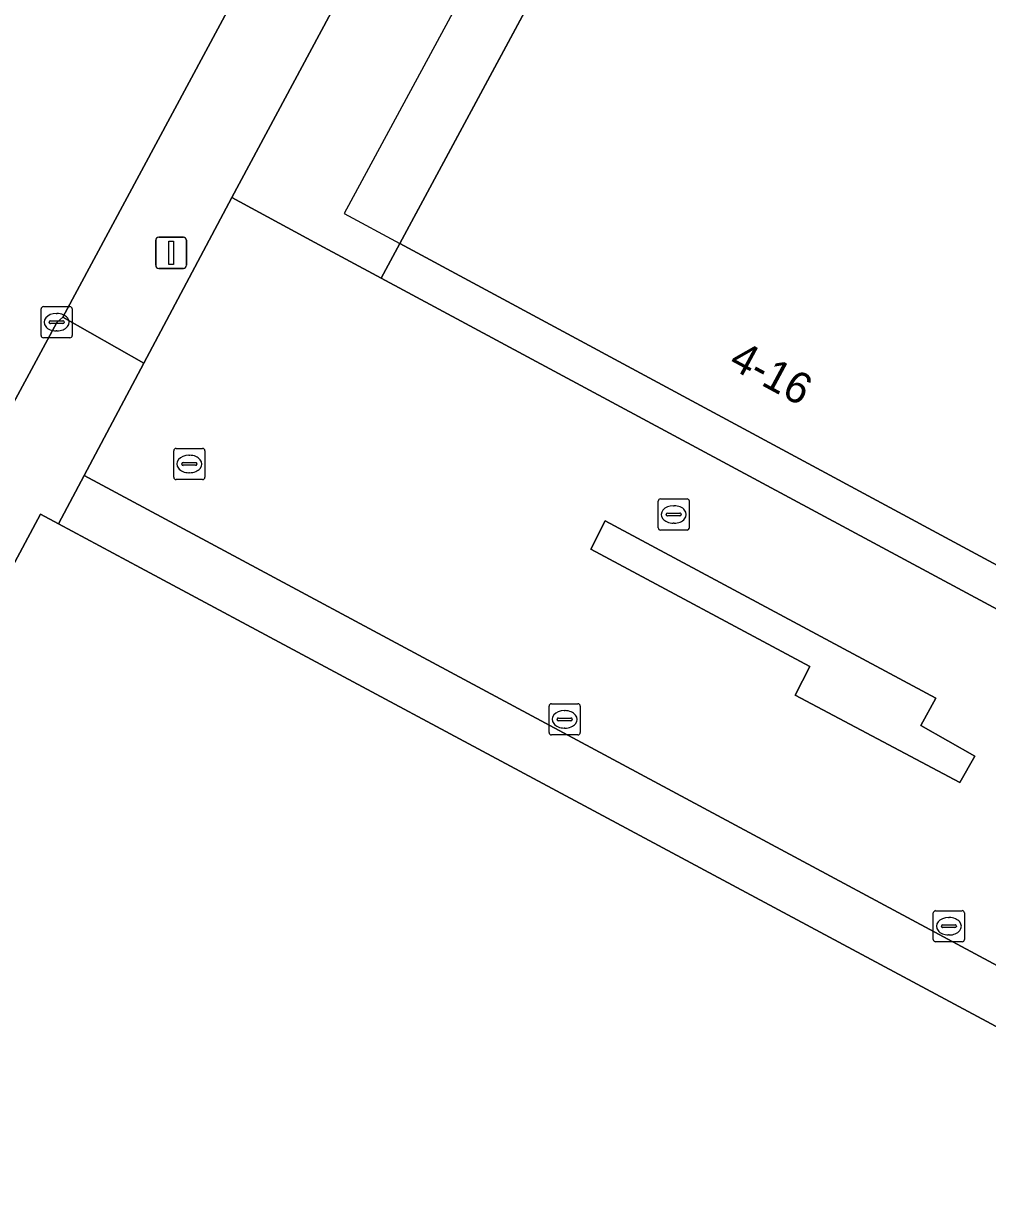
# Model space of a CAD drawing. Extents: x 159489 to 160304, y 383825 to 384531.
# Drawn here: x 159916.31 to 159947.25, y 384180.66 to 384218.65 of the extents above; entities that cross this region are included whole.
import ezdxf

# ---------------------------------------------------------------- set-up
doc = ezdxf.new("R2010")
doc.units = 0
for name, color, linetype in [('IMGEO_Groenvoorziening', 7, 'Continuous'), ('IMGEO_Kolk', 7, 'Continuous'), ('IMGEO_Lichtmast', 7, 'Continuous'), ('IMGEO_OVBaan_gesloten', 7, 'Continuous'), ('IMGEO_Pand', 7, 'Continuous'), ('IMGEO_Pand_nummerreeks', 7, 'Continuous'), ('IMGEO_Pand_overbouw', 7, 'Continuous'), ('IMGEO_Rioolput', 7, 'Continuous'), ('IMGEO_Voetpad_open', 7, 'Continuous')]:
    doc.layers.add(name, color=color, linetype=linetype)

msp = doc.modelspace()

# ---------------------------------------------------------------- linework, layer by layer
at = {"layer": 'IMGEO_Groenvoorziening'}
for points in [[(159982.197, 384221.174), (159967.686, 384229.02), (159951.577, 384199.109), (159928.39, 384211.596), (159927.794, 384210.489), (159967.949, 384188.903), (159982.328, 384181.173), (159984.895, 384182.371), (159986.818, 384178.787), (159991.4, 384176.315), (159993.92, 384177.521), (159995.948, 384173.906), (160023.092, 384159.367), (160025.82, 384157.906), (160029.234, 384164.348)], [(159946.374, 384194.291), (159946.851, 384195.146), (159945.113, 384196.129), (159945.604, 384197.003), (159934.981, 384202.69), (159934.517, 384201.79), (159941.552, 384198.022), (159941.079, 384197.098)]]:
    msp.add_lwpolyline(points, close=True, dxfattribs=at)
at = {"layer": 'IMGEO_Kolk'}
for p, q in [((159916.867, 384208.644), (159916.867, 384209.496)), ((159916.942, 384209.57), (159917.794, 384209.57)), ((159917.868, 384209.496), (159917.868, 384208.644)), ((159917.126, 384209.064), (159917.126, 384209.076)), ((159917.169, 384209.113), (159917.567, 384209.113)), ((159917.355, 384209.35), (159917.38, 384209.35)), ((159917.61, 384209.076), (159917.61, 384209.064)), ((159917.564, 384209.027), (159917.166, 384209.027)), ((159917.378, 384208.79), (159917.353, 384208.79)), ((159917.794, 384208.57), (159916.942, 384208.57)), ((159936.758, 384203.4), (159937.61, 384203.4)), ((159936.683, 384202.474), (159936.683, 384203.326)), ((159937.171, 384203.18), (159937.196, 384203.18)), ((159937.684, 384203.326), (159937.684, 384202.474)), ((159936.942, 384202.894), (159936.942, 384202.906)), ((159937.38, 384202.857), (159936.982, 384202.857)), ((159936.985, 384202.943), (159937.383, 384202.943)), ((159937.194, 384202.62), (159937.169, 384202.62)), ((159937.426, 384202.906), (159937.426, 384202.894)), ((159937.61, 384202.4), (159936.758, 384202.4)), ((159933.18, 384195.897), (159933.18, 384196.749)), ((159933.255, 384196.823), (159934.107, 384196.823)), ((159933.668, 384196.603), (159933.693, 384196.603)), ((159934.181, 384196.749), (159934.181, 384195.897)), ((159933.439, 384196.317), (159933.439, 384196.329)), ((159933.877, 384196.28), (159933.479, 384196.28)), ((159933.482, 384196.366), (159933.88, 384196.366)), ((159933.923, 384196.329), (159933.923, 384196.317)), ((159934.107, 384195.823), (159933.255, 384195.823)), ((159933.691, 384196.043), (159933.666, 384196.043)), ((159945.518, 384189.256), (159945.518, 384190.108)), ((159945.593, 384190.182), (159946.445, 384190.182)), ((159946.519, 384190.108), (159946.519, 384189.256)), ((159945.777, 384189.676), (159945.777, 384189.688)), ((159945.82, 384189.725), (159946.218, 384189.725)), ((159946.006, 384189.962), (159946.031, 384189.962)), ((159946.261, 384189.688), (159946.261, 384189.676)), ((159946.215, 384189.639), (159945.817, 384189.639)), ((159946.029, 384189.402), (159946.004, 384189.402)), ((159946.445, 384189.182), (159945.593, 384189.182))]:
    msp.add_line(p, q, dxfattribs=at)
for points in [[(159916.867, 384208.644), (159916.867, 384209.496)], [(159916.942, 384209.57), (159917.794, 384209.57)], [(159917.868, 384209.496), (159917.868, 384208.644)], [(159917.794, 384208.57), (159916.942, 384208.57)], [(159936.758, 384203.4), (159937.61, 384203.4)], [(159936.683, 384202.474), (159936.683, 384203.326)], [(159937.684, 384203.326), (159937.684, 384202.474)], [(159937.61, 384202.4), (159936.758, 384202.4)], [(159933.18, 384195.897), (159933.18, 384196.749)], [(159933.255, 384196.823), (159934.107, 384196.823)], [(159934.181, 384196.749), (159934.181, 384195.897)], [(159934.107, 384195.823), (159933.255, 384195.823)], [(159945.518, 384189.256), (159945.518, 384190.108)], [(159945.593, 384190.182), (159946.445, 384190.182)], [(159946.519, 384190.108), (159946.519, 384189.256)], [(159946.445, 384189.182), (159945.593, 384189.182)]]:
    msp.add_lwpolyline(points, dxfattribs=at)
for centre, radius, start, end in [((159916.944, 384209.494), 0.0765, 91.552, 178.448), ((159916.944, 384209.494), 0.0765, 91.552, 178.448), ((159917.792, 384209.494), 0.0765, 1.552, 88.448), ((159917.792, 384209.494), 0.0765, 1.552, 88.448), ((159917.166, 384209.073), 0.0403, 85.8775, 175.7526), ((159917.571, 384209.075), 0.0386, 1.7309, 96.639), ((159917.163, 384209.063), 0.0366, 178.938, 274.7102), ((159917.567, 384209.07), 0.043, 264.8664, 352.4533), ((159916.944, 384208.646), 0.0765, 181.552, 268.448), ((159916.944, 384208.646), 0.0765, 181.552, 268.448), ((159917.792, 384208.646), 0.0765, 271.552, 358.448), ((159917.792, 384208.646), 0.0765, 271.552, 358.448), ((159936.76, 384203.324), 0.0765, 91.552, 178.448), ((159936.76, 384203.324), 0.0765, 91.552, 178.448), ((159937.608, 384203.324), 0.0765, 1.552, 88.448), ((159937.608, 384203.324), 0.0765, 1.552, 88.448), ((159936.982, 384202.903), 0.0403, 85.8775, 175.7526), ((159936.979, 384202.893), 0.0366, 178.938, 274.7102), ((159937.383, 384202.9), 0.043, 264.8664, 352.4533), ((159937.387, 384202.905), 0.0386, 1.7309, 96.639), ((159936.76, 384202.476), 0.0765, 181.552, 268.448), ((159936.76, 384202.476), 0.0765, 181.552, 268.448), ((159937.608, 384202.476), 0.0765, 271.552, 358.448), ((159937.608, 384202.476), 0.0765, 271.552, 358.448), ((159933.257, 384196.747), 0.0765, 91.552, 178.448), ((159933.257, 384196.747), 0.0765, 91.552, 178.448), ((159934.105, 384196.747), 0.0765, 1.552, 88.448), ((159934.105, 384196.747), 0.0765, 1.552, 88.448), ((159933.479, 384196.326), 0.0403, 85.8775, 175.7526), ((159933.476, 384196.316), 0.0366, 178.938, 274.7102), ((159933.88, 384196.323), 0.043, 264.8664, 352.4533), ((159933.884, 384196.328), 0.0386, 1.7309, 96.639), ((159933.257, 384195.899), 0.0765, 181.552, 268.448), ((159933.257, 384195.899), 0.0765, 181.552, 268.448), ((159934.105, 384195.899), 0.0765, 271.552, 358.448), ((159934.105, 384195.899), 0.0765, 271.552, 358.448), ((159945.595, 384190.106), 0.0765, 91.552, 178.448), ((159945.595, 384190.106), 0.0765, 91.552, 178.448), ((159946.443, 384190.106), 0.0765, 1.552, 88.448), ((159946.443, 384190.106), 0.0765, 1.552, 88.448), ((159945.817, 384189.685), 0.0403, 85.8775, 175.7526), ((159946.222, 384189.687), 0.0386, 1.7309, 96.639), ((159945.814, 384189.675), 0.0366, 178.938, 274.7102), ((159946.218, 384189.682), 0.043, 264.8664, 352.4533), ((159945.595, 384189.258), 0.0765, 181.552, 268.448), ((159945.595, 384189.258), 0.0765, 181.552, 268.448), ((159946.443, 384189.258), 0.0765, 271.552, 358.448), ((159946.443, 384189.258), 0.0765, 271.552, 358.448)]:
    msp.add_arc(centre, radius, start, end, dxfattribs=at)
for centre, major_axis, ratio, start_param, end_param in [((159917.354, 384209.07), (-0.387, 0.002), 0.722429, 4.712389, 7.853982), ((159917.379, 384209.07), (-0.39, 0.002), 0.717154, 1.570796, 4.712389), ((159937.17, 384202.9), (-0.387, 0.002), 0.722429, 4.712389, 7.853982), ((159937.195, 384202.9), (-0.39, 0.002), 0.717154, 1.570796, 4.712389), ((159933.667, 384196.323), (-0.387, 0.002), 0.722429, 4.712389, 7.853982), ((159933.692, 384196.323), (-0.39, 0.002), 0.717154, 1.570796, 4.712389), ((159946.005, 384189.682), (-0.387, 0.002), 0.722429, 4.712389, 7.853982), ((159946.03, 384189.682), (-0.39, 0.002), 0.717154, 1.570796, 4.712389)]:
    msp.add_ellipse(centre, major_axis=major_axis, ratio=ratio, start_param=start_param, end_param=end_param, dxfattribs=at)
at = {"layer": 'IMGEO_Lichtmast'}
for p, q in [((159920.649, 384211.799), (159921.439, 384211.799)), ((159921.439, 384211.799), (159920.649, 384211.799)), ((159920.549, 384210.899), (159920.549, 384211.699)), ((159920.549, 384211.699), (159920.549, 384210.899)), ((159921.539, 384211.699), (159921.539, 384210.899)), ((159921.539, 384210.899), (159921.539, 384211.699)), ((159921.439, 384210.799), (159920.649, 384210.799)), ((159920.649, 384210.799), (159921.439, 384210.799))]:
    msp.add_line(p, q, dxfattribs=at)
msp.add_lwpolyline([(159920.969, 384211.674), (159921.119, 384211.674), (159921.119, 384210.924), (159920.969, 384210.924), (159920.969, 384211.674)], dxfattribs=at)
for centre, start, end in [((159920.649, 384211.699), 90, 180), ((159920.649, 384211.699), 90, 180), ((159921.439, 384211.699), 0, 90), ((159921.439, 384211.699), 360, 90), ((159920.649, 384210.899), 180, 270), ((159920.649, 384210.899), 180, 270), ((159921.439, 384210.899), 270, 0), ((159921.439, 384210.899), 270, 0)]:
    msp.add_arc(centre, 0.1, start, end, dxfattribs=at)
at = {"layer": 'IMGEO_OVBaan_gesloten'}
msp.add_lwpolyline([(159889.629, 384157.595), (159891.699, 384161.454), (159894.341, 384166.312), (159894.932, 384167.392), (159899.663, 384176.232), (159917.37, 384209.066), (159917.564, 384209.236), (159933.717, 384239.272), (159933.611, 384239.33), (159934.188, 384240.289), (159934.691, 384241.032), (159927.855, 384244.699), (159927.163, 384242.784), (159925.839, 384239.117), (159925.093, 384237.495), (159923.939, 384235.4), (159923.428, 384234.441), (159911.615, 384212.316), (159911.69, 384212.238), (159911.593, 384212.02), (159910.296, 384209.51), (159906.952, 384203.585), (159893.253, 384178.177), (159888.635, 384169.463)], dxfattribs=at)
at = {"layer": 'IMGEO_Pand'}
for points in [[(159967.686, 384229.02), (159944.524, 384241.543), (159928.39, 384211.596), (159951.577, 384199.109)], [(159920.064, 384201.185), (159917.432, 384202.595), (159916.85, 384202.907), (159901.938, 384175.054), (159901.96, 384175.043), (159906.775, 384172.478), (159912.035, 384169.676), (159918.126, 384166.432), (159935.251, 384157.25), (159940.225, 384154.583), (159948.39, 384150.205), (159951.365, 384148.61), (159970.476, 384138.363), (159972.877, 384137.075), (159988.602, 384128.644), (159993.803, 384125.855), (160002.485, 384121.2), (160003.04, 384122.23), (160003.607, 384123.282), (160007.121, 384129.803), (160017.466, 384149)]]:
    msp.add_lwpolyline(points, close=True, dxfattribs=at)
at = {"layer": 'IMGEO_Pand_overbouw'}
msp.add_lwpolyline([(159953.299, 384198.181), (159969.896, 384228.943), (159943.238, 384243.325), (159926.605, 384212.558), (159928.39, 384211.596), (159944.07, 384240.7), (159944.524, 384241.543), (159945.039, 384241.265), (159967.686, 384229.02), (159951.577, 384199.109)], close=True, dxfattribs=at)
at = {"layer": 'IMGEO_Rioolput'}
for p, q in [((159921.127, 384204.094), (159921.127, 384204.946)), ((159921.202, 384205.02), (159922.054, 384205.02)), ((159922.128, 384204.946), (159922.128, 384204.094)), ((159921.386, 384204.514), (159921.386, 384204.526)), ((159921.429, 384204.563), (159921.827, 384204.563)), ((159921.615, 384204.8), (159921.64, 384204.8)), ((159921.87, 384204.526), (159921.87, 384204.514)), ((159921.824, 384204.477), (159921.426, 384204.477)), ((159921.638, 384204.24), (159921.613, 384204.24)), ((159922.054, 384204.02), (159921.202, 384204.02))]:
    msp.add_line(p, q, dxfattribs=at)
for points in [[(159921.127, 384204.094), (159921.127, 384204.946)], [(159921.202, 384205.02), (159922.054, 384205.02)], [(159922.128, 384204.946), (159922.128, 384204.094)], [(159922.054, 384204.02), (159921.202, 384204.02)]]:
    msp.add_lwpolyline(points, dxfattribs=at)
for centre, radius, start, end in [((159921.204, 384204.944), 0.0765, 91.552, 178.448), ((159921.204, 384204.944), 0.0765, 91.552, 178.448), ((159922.052, 384204.944), 0.0765, 1.552, 88.448), ((159922.052, 384204.944), 0.0765, 1.552, 88.448), ((159921.426, 384204.523), 0.0403, 85.8775, 175.7526), ((159921.423, 384204.513), 0.0366, 178.938, 274.7102), ((159921.827, 384204.52), 0.043, 264.8664, 352.4533), ((159921.831, 384204.525), 0.0386, 1.7309, 96.639), ((159921.204, 384204.096), 0.0765, 181.552, 268.448), ((159921.204, 384204.096), 0.0765, 181.552, 268.448), ((159922.052, 384204.096), 0.0765, 271.552, 358.448), ((159922.052, 384204.096), 0.0765, 271.552, 358.448)]:
    msp.add_arc(centre, radius, start, end, dxfattribs=at)
for centre, major_axis, ratio, start_param, end_param in [((159921.614, 384204.52), (-0.387, 0.002), 0.722429, 4.712389, 7.853982), ((159921.639, 384204.52), (-0.39, 0.002), 0.717154, 1.570796, 4.712389)]:
    msp.add_ellipse(centre, major_axis=major_axis, ratio=ratio, start_param=start_param, end_param=end_param, dxfattribs=at)
at = {"layer": 'IMGEO_Voetpad_open'}
msp.add_lwpolyline([(159938.258, 384245.722), (159936.217, 384243.18), (159934.691, 384241.032), (159937.261, 384239.696), (159936.314, 384237.873), (159922.992, 384213.07), (159925.664, 384211.634), (159927.794, 384210.489), (159928.39, 384211.596), (159944.524, 384241.543), (159967.686, 384229.02), (159982.197, 384221.174), (160029.234, 384164.348), (160030.452, 384166.645), (160029.527, 384167.731), (159960.897, 384250.561)], dxfattribs=at)
for points in [[(159936.314, 384237.873), (159937.261, 384239.696), (159934.691, 384241.032), (159934.188, 384240.289), (159933.611, 384239.33), (159933.717, 384239.272), (159917.564, 384209.236), (159920.172, 384207.756), (159922.992, 384213.07)], [(159967.949, 384188.903), (159927.794, 384210.489), (159925.664, 384211.634), (159922.992, 384213.07), (159920.172, 384207.756), (159918.255, 384204.145), (160018.319, 384150.449), (160023.092, 384159.367), (159995.948, 384173.906), (159993.92, 384177.521), (159991.4, 384176.315), (159986.818, 384178.787), (159984.895, 384182.371), (159982.328, 384181.173)], [(159916.85, 384202.907), (159917.432, 384202.595), (159918.255, 384204.145), (159920.172, 384207.756), (159917.564, 384209.236), (159917.37, 384209.066), (159899.663, 384176.232), (159901.938, 384175.054)], [(159918.255, 384204.145), (159917.432, 384202.595), (159920.064, 384201.185), (160017.466, 384149), (160017.526, 384148.968), (160018.319, 384150.449)], [(159946.374, 384194.291), (159941.079, 384197.098), (159941.552, 384198.022), (159934.517, 384201.79), (159934.981, 384202.69), (159945.604, 384197.003), (159945.113, 384196.129), (159946.851, 384195.146)]]:
    msp.add_lwpolyline(points, close=True, dxfattribs=at)

# ---------------------------------------------------------------- texts
at = {"layer": 'IMGEO_Pand_nummerreeks'}
msp.add_text('4-16', height=1, rotation=331.6959, dxfattribs=at).set_placement((159938.905, 384207.637))

doc.saveas('drawing.dxf')
